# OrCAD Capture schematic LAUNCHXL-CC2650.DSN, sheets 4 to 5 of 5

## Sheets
4 2_Peripherals: size A3
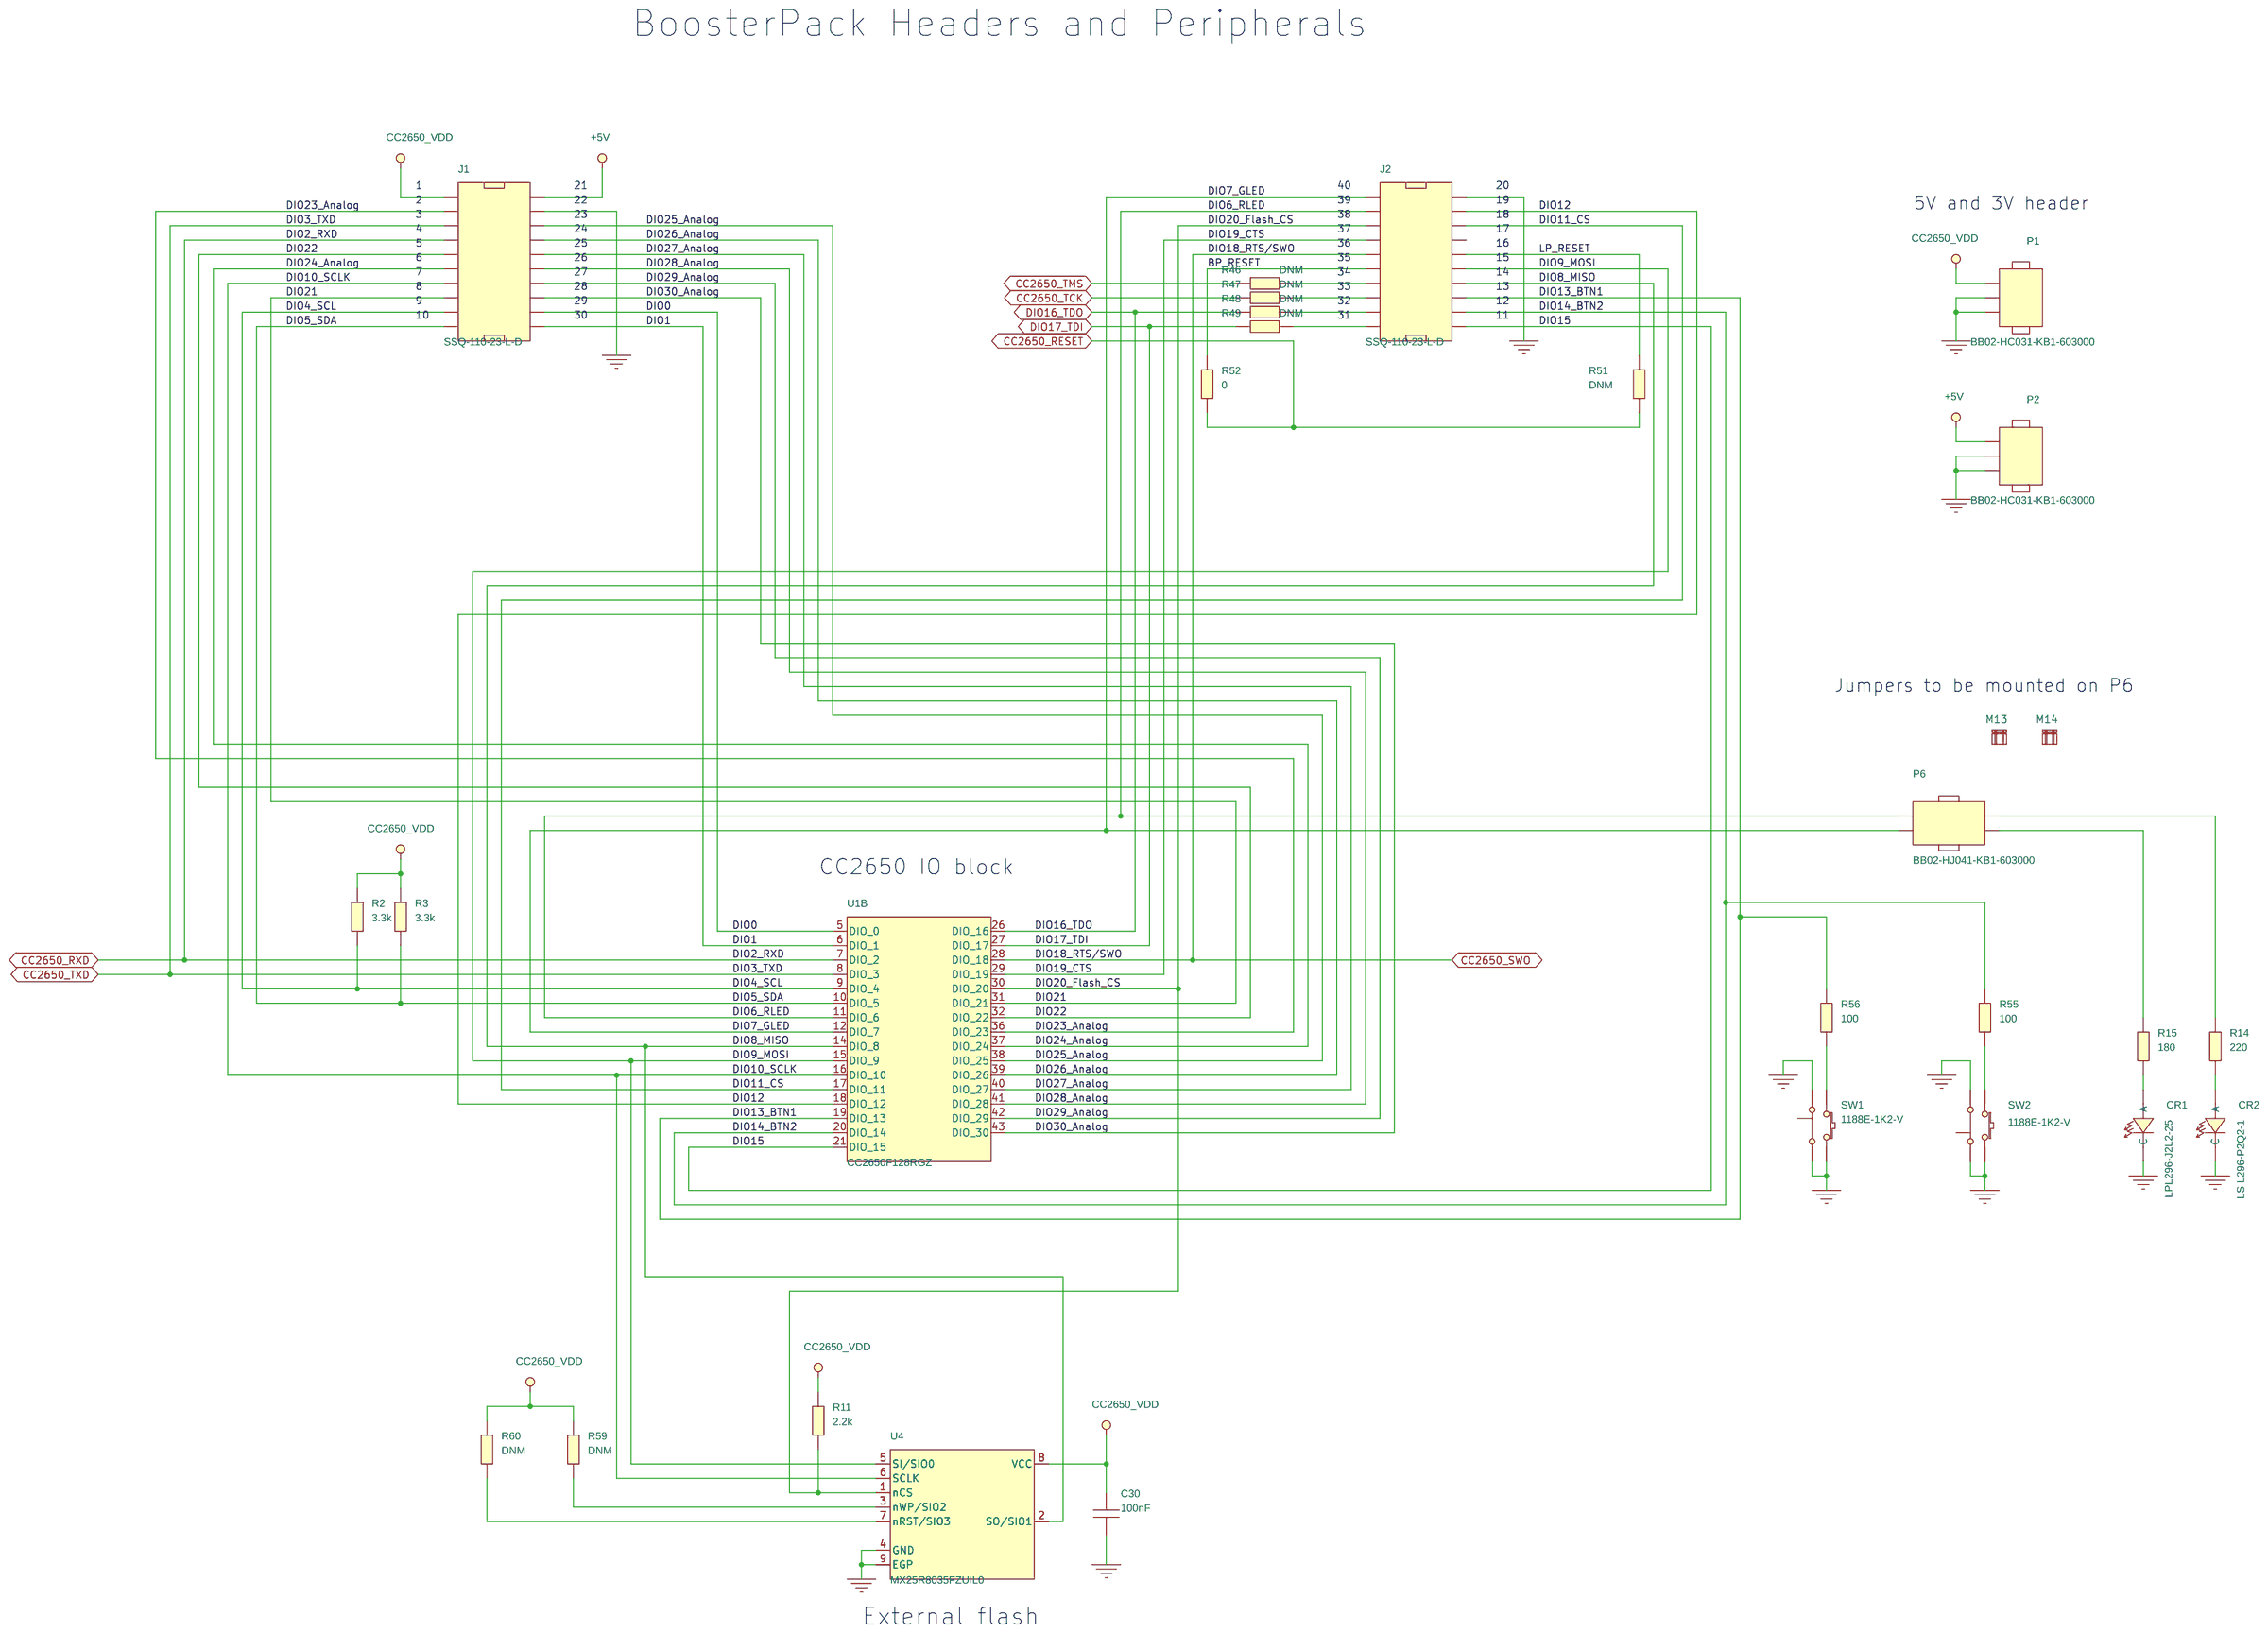
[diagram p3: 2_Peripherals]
5 1_CC2650RF: size A4
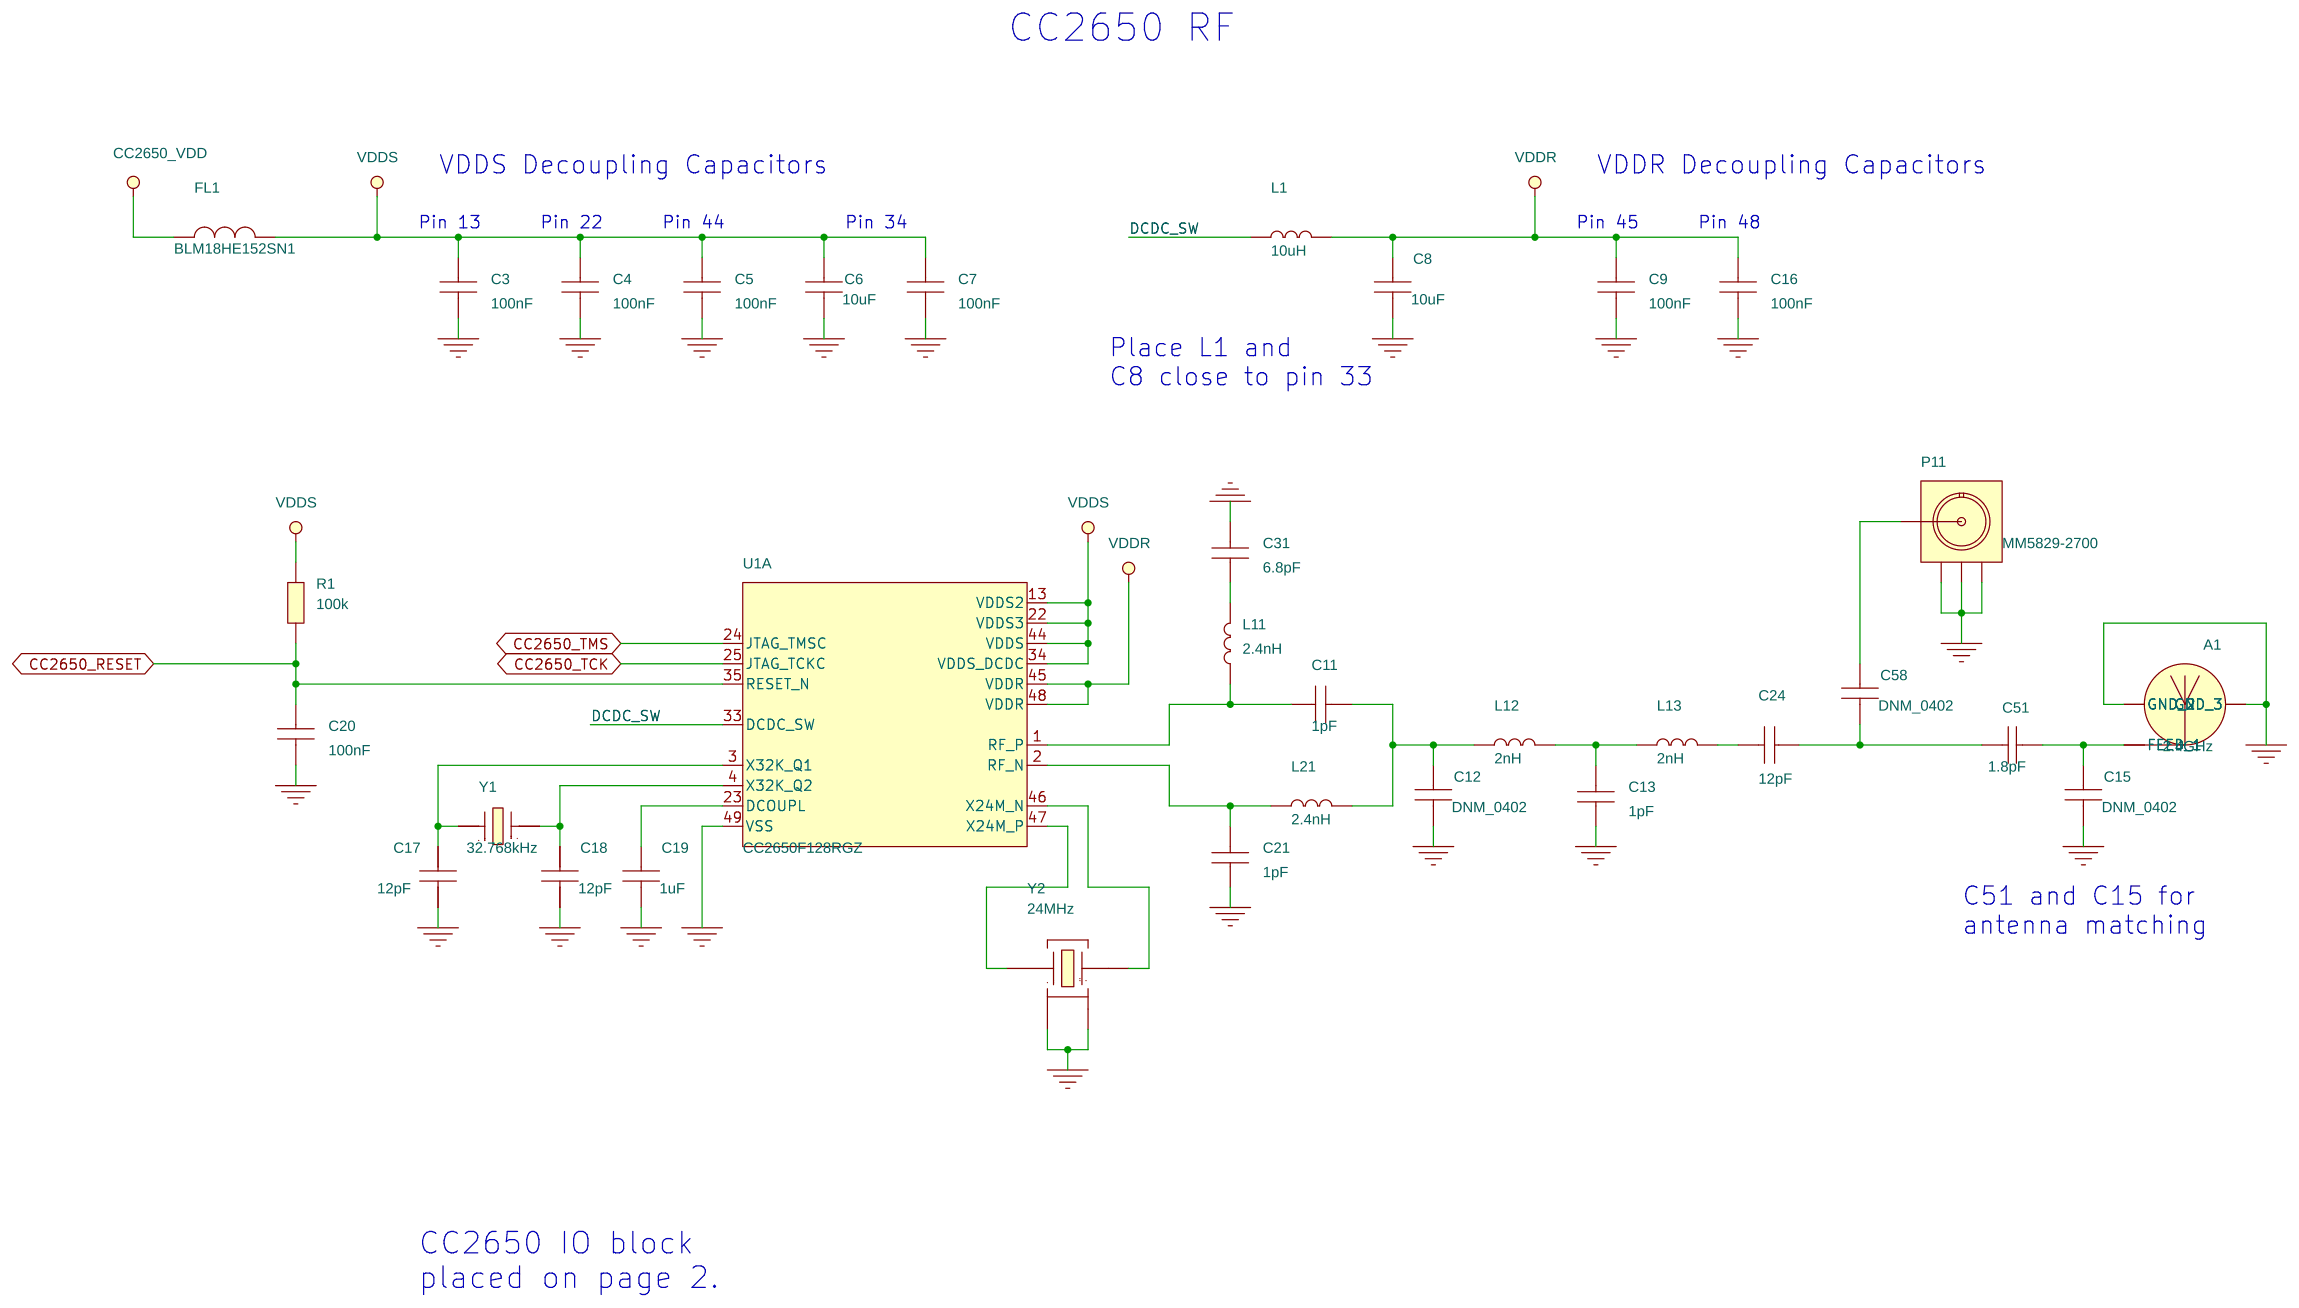
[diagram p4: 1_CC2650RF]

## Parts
sheet 1_CC2650RF
A1  2.4GHz  [ANTENNA_DN007AN]
C3  100nF  [CAPC1005X60B2N]
C4  100nF  [CAPC1005X60B2N]
C5  100nF  [CAPC1005X60B2N]
C6  10uF  [CAPC1608X90N]
C7  100nF  [CAPC1005X60B2N]
C8  10uF  [CAPC1608X90N]
C9  100nF  [CAPC1005X60B2N]
C11  1pF  [CAPC1005X60B2N]
C12  DNM_0402  [CAPC1005X60B2N]
C13  1pF  [CAPC1005X60B2N]
C15  DNM_0402  [CAPC1005X60B2N]
C16  100nF  [CAPC1005X60B2N]
C17  12pF  [CAPC1005X60B2N]
C18  12pF  [CAPC1005X60B2N]
C19  1uF  [CAPC1005X60B2N]
C20  100nF  [CAPC1005X60B2N]
C21  1pF  [CAPC1005X60B2N]
C24  12pF  [CAPC1005X60B2N]
C31  6.8pF  [CAPC1005X60N]
C51  1.8pF  [CAPC1005X60B2N]
C58  DNM_0402  [CAPC1005X60B2N]
FL1  BLM18HE152SN1  [FIL_BLM18HE152SN1DL]
L1  10uH  [INDC2012X150L]
L11  2.4nH  [INDC1005X60B2N]
L12  2nH  [INDC1005X60B2N]
L13  2nH  [INDC1005X60B2N]
L21  2.4nH  [INDC1005X60B2N]
P11  MM5829-2700  [MURATA_MM58292700RJ4_A2N]
R1  100k  [RESC1005X40B2N]
U1  CC2650F128RGZ  [QFNFC50P700X700X80-49CL]  (sections A,B)
Y1  32.768kHz  [XTAL_FC-135N]
Y2  24MHz  [OSCCC250X320X60-4L]
sheet 2_Peripherals
C30  100nF  [CAPC1005X60B2N]
CR1  LPL296-J2L2-25  [LEDC1707X65L]
CR2  LS L296-P2Q2-1  [LEDC1708X67L]
J1  SSQ-110-23-L-D  [SAMTEC_SSQ11023LD_A2B]
J2  SSQ-110-23-L-D  [SAMTEC_SSQ11023LD_A2B]
M13  SNT-100-BK-G
M14  SNT-100-BK-G
P1  BB02-HC031-KB1-603000  [GRADCONN_BB02HC031KB1603000_A2B]
P2  BB02-HC031-KB1-603000  [GRADCONN_BB02HC031KB1603000_A2B]
P6  BB02-HJ041-KB1-603000  [GRADCONN_BB02HJ041KB1603000_A2B]
R2  3.3k  [RESC1005X40B2N]
R3  3.3k  [RESC1005X40B2N]
R11  2.2k  [RESC1005X40B2N]
R14  220  [RESC1005X40B2N]
R15  180  [RESC1005X40B2N]
R46  DNM  [RESC1608X55N]
R47  DNM  [RESC1608X55N]
R48  DNM  [RESC1608X55N]
R49  DNM  [RESC1608X55N]
R51  DNM  [RESC1608X55N]
R52  0  [RESC1608X55N]
R55  100  [RESC1005X40B2N]
R56  100  [RESC1005X40B2N]
R59  DNM  [RESC1005X40B2N]
R60  DNM  [RESC1005X40B2N]
SW1  1188E-1K2-V  [SW_1188E1K2V_A2N]
SW2  1188E-1K2-V  [SW_1188E1K2V_A2N]
U4  MX25R8035FZUIL0  [SON50P300X200X60-9B2L]

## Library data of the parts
A1 = ANTENNA_DN007: MECHANIC, 2.4GHz INVERTED F ANTENNA, SMD; AutoDoc File: http://notefied-dynamic-precision.com/DB/Apps/Desktop/Item/Object.aspx?id=85542; Budget Currency: N/A; Budget Price: N/A; Datasheet URL 1: http://www.ti.com/lit/er/swrz002d/swrz002d.pdf; Datasheet URL 2: http://www.ti.com/lit/ds/symlink/cc2500.pdf; Definied Quality: INDUSTRIAL; Esd Level: HBM 500V; FPLIST: ANTENNA_DN007N,ANTENNA_DN007AN,; Last Time Buy: N/A; Lead Time: N/A; MPN: DN007; MPN Status: ACTIVE; MSL: N/A; MTBF: N/A; MTBF Standard: N/A; Manufacturer: TEXAS INSTRUMENTS; Max Oper Temp: +85DEGC; Min Oper Temp: -40DEGC; Mounting Type: SMD; NOTE Status: PREFERRED; Old Footprint: ANTENNA_DN007N,ANTENNA_DN007AN; Packing Size: N/A; Packing Type: N/A; Part Number: 13-00347; Part Type: MECHANIC\ANTENNA; Revision: R006; RoHS Status: LEADED; WEIGHT: N/A
C3-C5 C7 C9 C16 C20 = CAPACITOR: CAPACITOR, CERAMIC X7R, 100nF, 6.3V, -10%/+10%, -55DEGC/+125DEGC, 0402, SMD; AutoDoc File: https://notefied-dynamic-precision.com/DB/Apps/Desktop/Item/Object.aspx?id=113338; BU Name: TEXAS INSTRUMENTS NORWAY; Budget Currency: EUR; Budget Price: 0.007; Country of Origin: PHILIPPINES; Datasheet URL 1: http://psearch.murata.com/capacitor/product/GRM155R70J104KA01%23.pdf; Datasheet URL 2: http://search.murata.co.jp/Ceramy/image/img/w_hinm/L0005E.pdf; Dielectric Type: X7R; Last Time Buy: N/A; Lead Time: 14; LifeCycle Status: ACTIVE; MPN: GRM155R70J104KA01D; MPN Status: ACTIVE; Manufacturer: MURATA; Max Oper Temp: +125DEGC; Max Tol: +10%; Min Oper Temp: -55DEGC; Min Tol: -10%; Mounting Type: SMD; NOTE Status: PREFERRED; Old Footprint: CAPC1005X60N,0402; PCB Package: 0402; Packing Size: 10000; Packing Type: TAPE_&_REEL; Part Number: 02-07610; Part Type: CAPACITOR\CERAMIC\0402\STANDARD; Revision: R000; RoHS Status: ROHS_COMPLIANT; Rtd Voltage: 6.3V; Vendor: MURATA; Vendor Part Number: GRM155R70J104KA01D; Vendor Part Status: NRND; WEIGHT: 0.0016g
C6 C8 = CAPACITOR: CAPACITOR, CERAMIC X5R, 10uF, 6.3V, -20%/+20%, -55DEGC/+85DEGC, 0603, SMD; ALT_SYMBOLS: CAPC1608X90L,CAPC1608X90M; AutoDoc File: http://notefied-dynamic-precision.com/DB/Apps/Desktop/Item/Object.aspx?id=74686; Budget Currency: EUR; Budget Price: 0.067; Datasheet URL 1: http://search.murata.co.jp/Ceramy/image/img/w_hinm/L0005E.pdf; Datasheet URL 2: http://psearch.murata.com/capacitor/product/GRM188R60J106ME47%23.pdf; Definied Quality: INDUSTRIAL; Dielectric Type: X5R; Esd Level: N/A; FPLIST: CAPC1608X90N,CAPC1608X90L,CAPC1608X90M; Last Time Buy: N/A; Lead Time: 20; MPN: GRM188R60J106ME47D; MPN Status: NRND; MSL: 1; MTBF: N/A; MTBF Standard: N/A; Manufacturer: MURATA; Max Oper Temp: +85DEGC; Max Tol: +20%; Min Oper Temp: -55DEGC; Min Tol: -20%; Mounting Type: SMD; NOTE Status: PREFERRED; PCB Package: 0603; Packing Size: 4000; Packing Type: TAPE_&_REEL; Part Number: 02-02419; Part Type: CAPACITOR\CERAMIC\0603; Revision: R003; RoHS Status: ROHS_COMPLIANT; Rtd Voltage: 6.3V; WEIGHT: 0.0063g
C11 C13 C21 = CAPACITOR: CAPACITOR, CERAMIC C0G/NP0, 1pF, 50V, -0.25pF/ +0.25pF, -55DEGC/+125DEGC, 0402, SMD; AutoDoc File: https://notefied-dynamic-precision.com/DB/Apps/Desktop/Item/Object.aspx?id=113355; BU Name: TEXAS INSTRUMENTS NORWAY; Budget Currency: EUR; Budget Price: 0.006; Country of Origin: PHILIPPINES; Datasheet URL 1: http://psearch.murata.com/capacitor/product/GRM1555C1H1R0CA01%23.pdf; Datasheet URL 2: http://search.murata.co.jp/Ceramy/image/img/w_hinm/L0005E.pdf; Dielectric Type: C0G/NP0; Last Time Buy: N/A; Lead Time: 12; MPN: GRM1555C1H1R0CA01D; MPN Status: ACTIVE; Manufacturer: MURATA; Max Oper Temp: +125DEGC; Max Tol: +0.25pF; Min Oper Temp: -55DEGC; Min Tol: -0.25pF; Mounting Type: SMD; NOTE Status: PREFERRED; Old Footprint: CAPC1005X60N; PCB Package: 0402; Packing Size: 10000; Packing Type: TAPE_&_REEL; Part Number: 02-07627; Part Type: CAPACITOR\CERAMIC\0402\STANDARD; Revision: R000; RoHS Status: ROHS_COMPLIANT; Rtd Voltage: 50V; Vendor: MURATA; Vendor Part Number: GRM1555C1H1R0CA01D; Vendor Part Status: ACTIVE; WEIGHT: 0.0016g
C12 C15 C58 = CAPACITOR: CAPACITOR, CERAMIC, TBD, -55DEGC/+125DEGC, 0402, DNM, SMD; AutoDoc File: https://notefied-dynamic-precision.com/DB/Apps/Desktop/Item/Object.aspx?id=113344; BU Name: TEXAS INSTRUMENTS NORWAY; Budget Currency: USD; Budget Price: 0.00589; Country of Origin: MISSING INFO; Datasheet URL 1: N/A; Datasheet URL 2: N/A; Dielectric Type: MISSING-INFO; Last Time Buy: N/A; Lead Time: N/A; MPN: CAPACITOR_0402_DNM_N/A_M; MPN Status: ACTIVE; Manufacturer: Manufacturer selection; Max Oper Temp: +125DEGC; Min Oper Temp: -55DEGC; Mounting Type: SMD; NOTE Status: PREFERRED; Old Footprint: CAPC1005X60N; PCB Package: 0402; Packing Size: 10000; Packing Type: TAPE_&_REEL; Part Number: 02-07616; Part Type: CAPACITOR\CERAMIC\0402\STANDARD; Revision: R000; RoHS Status: MISSING_INFO; Vendor: MANUFACTURER SELECTION; Vendor Part Number: CAPACITOR_0402_DNM_N/A_M; Vendor Part Status: ACTIVE; Weight: N/A
C17 C18 = CAPACITOR: CAPACITOR, CERAMIC C0G/NP0, 12pF, 50V, -5%/+5%, -55DEGC/+125DEGC, 0402, SMD; AutoDoc File: https://notefied-dynamic-precision.com/DB/Apps/Desktop/Item/Object.aspx?id=113340; BU Name: TEXAS INSTRUMENTS NORWAY; Budget Currency: USD; Budget Price: 0.00589; Country of Origin: MISSING INFO; Datasheet URL 1: N/A; Datasheet URL 2: N/A; Definied Quality: INDUSTRIAL; Dielectric Type: C0G/NP0; Esd Level: N/A; Last Time Buy: N/A; Lead Time: N/A; LifeCycle Status: ACTIVE; MPN: CAPACITOR_0402_12pF_C0G/NP0_M_+/-5%_50V; MPN Status: ACTIVE; MSL: N/A; MTBF: N/A; MTBF Standard: N/A; Manufacturer: MANUFACTURER SELECTION; Max Oper Temp: +125DEGC; Max Tol: +5%; Min Oper Temp: -55DEGC; Min Tol: -5%; Mounting Type: SMD; NOTE Status: PREFERRED; Old Footprint: CAPC1005X60N; PCB Package: 0402; Packing Size: 10000; Packing Type: TAPE_&_REEL; Part Number: 02-07612; Part Type: CAPACITOR\CERAMIC\0402\STANDARD; Revision: R000; RoHS Status: ROHS_COMPLIANT; Rtd Voltage: 50V; Vendor: MANUFACTURER SELECTION; Vendor Part Number: CAPACITOR_0402_12pF_C0G/NP0_M_+/-5%_50V; Vendor Part Status: ACTIVE; WEIGHT: N/A
C19 = CAPACITOR: CAPACITOR, CERAMIC X5R, 1uF, 10V, -10%/+10%, -55DEGC/+85DEGC, 0402, SMD; AutoDoc File: https://notefied-dynamic-precision.com/DB/Apps/Desktop/Item/Object.aspx?id=113339; BU Name: TEXAS INSTRUMENTS NORWAY; Budget Currency: EUR; Budget Price: 0.019; Country of Origin: PHILIPPINES,CHINA; Datasheet URL 1: http://psearch.murata.com/capacitor/product/GRM155R61A105KE15%23.pdf; Datasheet URL 2: http://search.murata.co.jp/Ceramy/image/img/w_hinm/L0005E.pdf; Definied Quality: INDUSTRIAL; Dielectric Type: X5R; Esd Level: N/A; Last Time Buy: N/A; Lead Time: 12; MPN: GRM155R61A105KE15D; MPN Status: ACTIVE; MSL: 1; MTBF: N/A; MTBF Standard: N/A; Manufacturer: MURATA; Max Oper Temp: +85DEGC; Max Tol: +10%; Min Oper Temp: -55DEGC; Min Tol: -10%; Mounting Type: SMD; NOTE Status: PREFERRED; Old Footprint: CAPC1005X60N,0402; PCB Package: 0402; Packing Size: 10000; Packing Type: TAPE_&_REEL; Part Number: 02-07611; Part Type: CAPACITOR\CERAMIC\0402\STANDARD; Revision: R000; RoHS Status: ROHS_COMPLIANT; Rtd Voltage: 10V; Vendor: MURATA; Vendor Part Number: GRM155R61A105KE15D; Vendor Part Status: NRND; WEIGHT: 0.0016g
C24 = CAPACITOR: CAPACITOR, CERAMIC C0G/NP0, 12pF, 50V, -5%/+5%, -55DEGC/+125DEGC, 0402, SMD; AutoDoc File: https://notefied-dynamic-precision.com/DB/Apps/Desktop/Item/Object.aspx?id=113345; BU Name: TEXAS INSTRUMENTS NORWAY; Budget Currency: EUR; Budget Price: 0.007; Country of Origin: PHILIPPINES; Datasheet URL 1: http://psearch.murata.com/capacitor/product/GRM1555C1H120JA01%23.pdf; Datasheet URL 2: http://search.murata.co.jp/Ceramy/image/img/w_hinm/L0005E.pdf; Dielectric Type: C0G/NP0; Last Time Buy: N/A; Lead Time: 12; MPN: GRM1555C1H120JA01D; MPN Status: ACTIVE; Manufacturer: MURATA; Max Oper Temp: +125DEGC; Max Tol: +5%; Min Oper Temp: -55DEGC; Min Tol: -5%; Mounting Type: SMD; NOTE Status: PREFERRED; Old Footprint: CAPC1005X60N; PCB Package: 0402; Packing Size: 10000; Packing Type: TAPE_&_REEL; Part Number: 02-07617; Part Type: CAPACITOR\CERAMIC\0402\STANDARD; Revision: R000; RoHS Status: ROHS_COMPLIANT; Rtd Voltage: 50V; Vendor: MURATA; Vendor Part Number: GRM1555C1H120JA01D; Vendor Part Status: ACTIVE; WEIGHT: 0.0016g
C31 = CAPACITOR: CAPACITOR, CERAMIC C0G/NP0, 6.8pF, 50V, -0.25pF/+0.25pF, -55DEGC/+125DEGC, 0402, SMD; ALT_SYMBOLS: CAPC1005X60L,CAPC1005X60M; AutoDoc File: https://notefied-dynamic-precision.com/DB/Apps/Desktop/Item/Object.aspx?id=84868; BU Name: DYNAMIC PRECISION GDANSK; Budget Currency: EUR; Budget Price: 0.007; Country of Origin: PHILIPPINES; Datasheet URL 1: http://psearch.murata.com/capacitor/product/GRM1555C1H6R8CA01%23.pdf; Datasheet URL 2: http://search.murata.co.jp/Ceramy/image/img/w_hinm/L0005E.pdf; Dielectric Type: C0G/NP0; Last Time Buy: N/A; Lead Time: 16; MPN: GRM1555C1H6R8CA01D; MPN Status: ACTIVE; Manufacturer: MURATA; Max Oper Temp: +125DEGC; Max Tol: +0.25pF; Min Oper Temp: -55DEGC; Min Tol: -0.25pF; Mounting Type: SMD; NOTE Status: PREFERRED; PCB Package: 0402; Packing Size: 10000; Packing Type: TAPE_&_REEL; Part Number: 02-04169; Part Type: CAPACITOR\CERAMIC\0402\STANDARD; Revision: R000; RoHS Status: ROHS_COMPLIANT; Rtd Voltage: 50V; Vendor: MURATA; Vendor Part Number: GRM1555C1H6R8CA01D; Vendor Part Status: ACTIVE; WEIGHT: 0.0016g
C51 = CAPACITOR_HOR: CAPACITOR, CERAMIC C0G/NP0, 1.8pF, 50V, -0.25pF, +0.25pF, -55DEGC/+125DEGC, 0402, SMD; AutoDoc File: https://notefied-dynamic-precision.com/DB/Apps/Desktop/Item/Object.aspx?id=113348; BU Name: TEXAS INSTRUMENTS NORWAY; Budget Currency: EUR; Budget Price: 0.007; Country of Origin: PHILIPPINES; Datasheet URL 1: http://psearch.murata.com/capacitor/product/GRM1555C1H1R8CA01%23.pdf; Datasheet URL 2: http://search.murata.co.jp/Ceramy/image/img/w_hinm/L0005E.pdf; Definied Quality: INDUSTRIAL; Dielectric Type: C0G/NP0; Esd Level: N/A; Last Time Buy: N/A; Lead Time: 12; LifeCycle Status: ACTIVE; MPN: GRM1555C1H1R8CA01D; MPN Status: ACTIVE; MSL: 1; MTBF: N/A; MTBF Standard: N/A; Manufacturer: MURATA; Max Oper Temp: +125DEGC; Max Tol: +0.25pF; Min Oper Temp: -55DEGC; Min Tol: -0.25pF; Mounting Type: SMD; NOTE Status: PREFERRED; Old Footprint: CAPC1005X60N; PCB Package: 0402; Packing Size: 10000; Packing Type: TAPE_&_REEL; Part Number: 02-07620; Part Type: CAPACITOR\CERAMIC\0402\STANDARD; Revision: R000; RoHS Status: ROHS_COMPLIANT; Rtd Voltage: 50V; Vendor: MURATA; Vendor Part Number: GRM1555C1H1R8CA01D; Vendor Part Status: ACTIVE; WEIGHT: 0.0016g
FL1 = FILTER_2PIN: FILTER, EMI, 1500@100MHz, -55DEGC/+125DEGC, 0603, SMD; ALT_SYMBOLS: FIL_BLM18HE152SN1DL,FIL_BLM18HE152SN1DM; AutoDoc File: http://notefied-dynamic-precision.com/DB/Apps/Desktop/Item/Object.aspx?id=85575; Budget Currency: EUR; Budget Price: 0.085; Datasheet URL 1: http://search.murata.co.jp/Ceramy/image/img/PDF/ENG/L0110S0101BLM18H.pdf; Datasheet URL 2: http://search.murata.co.jp/Ceramy/image/img/PDF/ENG/L0110S0101BLM18H.pdf; FPLIST: FIL_BLM18HE152SN1DN,FIL_BLM18HE152SN1DL,FIL_BLM18HE152SN1DM; Impedance: 1500@100MHz; Lead Time: 26; MPN: BLM18HE152SN1D; MPN Status: ACTIVE; Manufacturer: MURATA; Max Oper Temp: +125DEGC; Max Tol: +25%; Min Oper Temp: -55DEGC; Min Tol: -25%; Mounting Type: SMD; NOTE Status: PREFERRED; Old Footprint: FIL_BLM18HE152SN1DN; PCB Package: 0603; Packing Size: 4000; Packing Type: TAPE_&_REEL; Part Number: 04-00470; Part Type: FILTER\EMI\0603; Revision: R001; RoHS Status: ROHS_COMPLIANT; Rtd Current: 0.5A; WEIGHT: 0.006g
L1 = INDUCTOR: INDUCTOR, CHIP, 10uH, -20%/+20%, 0.11A, -40DEGC/+85DEGC, 0805, SMD; ALT_SYMBOLS: INDC2012X150L,INDC2012X150M; AutoDoc File: http://notefied-dynamic-precision.com/DB/Apps/Desktop/Item/Object.aspx?id=84960; Budget Currency: USD; Budget Price: 0.04; Datasheet URL 1: http://www.yuden.co.jp/us/product/pdf/mlci_all_e.pdf; Datasheet URL 2: http://www.yuden.co.jp/us/product/pdf/mlci_all_e.pdf; FPLIST: INDC2012X150N,INDC2012X150L,INDC2012X150M; Frequency: 24MHz; MPN: CKS2125100M-T; MPN Status: ACTIVE; Manufacturer: TAIYO YUDEN; Max Oper Temp: +85DEGC; Max Tol: +20%; Min Oper Temp: -40DEGC; Min Tol: -20%; Mounting Type: SMD; NOTE Status: PREFERRED; Old Footprint: INDC2012X150N; PCB Package: 0805; Packing Size: 4000; Packing Type: TAPE_&_REEL; Part Number: 03-06514; Part Type: INDUCTOR\CHIP\0805; Revision: R001; RoHS Status: ROHS_COMPLIANT; Rtd Current: 0.11A
L11 L21 = INDUCTOR: INDUCTOR, RF, CHIP, NON-MAGNETIC CORE, 2.4nH, -0.3nH/+0.3nH, 0.3A, -55DEGC/+125DEGC, 0402, SMD; AutoDoc File: https://notefied-dynamic-precision.com/DB/Apps/Desktop/Item/Object.aspx?id=113363; BU Name: TEXAS INSTRUMENTS NORWAY; Budget Currency: EUR; Budget Price: 0.031; Core Material: NON-MAGNETIC; Country of Origin: JAPAN,SINGAPORE; Datasheet URL 1: http://psearch.murata.com/inductor/product/LQG15HS2N4S02%23.pdf; Datasheet URL 2: N/A; Frequency: 6GHz; Last Time Buy: N/A; Lead Time: 9; MPN: LQG15HN2N4S02D; MPN Status: ACTIVE; Manufacturer: MURATA; Max Oper Temp: +125DEGC; Max Tol: +0.3nH; Min Oper Temp: -55DEGC; Min Tol: -0.3nH; Mounting Type: SMD; NOTE Status: PREFERRED; Old Footprint: INDC1005X60N; PCB Package: 0402; Packing Size: 10000; Packing Type: TAPE_&_REEL; Part Number: 03-07526; Part Type: INDUCTOR\RF\CHIP\0402; Revision: R000; RoHS Status: ROHS_COMPLIANT; Rtd Current: 0.3A; Vendor: MURATA; Vendor Part Number: LQG15HS2N4S02D; Vendor Part Status: ACTIVE; WEIGHT: 0.001g
L12 L13 = INDUCTOR: INDUCTOR, RF, CHIP, NON-MAGNETIC CORE, 2nH, -0.3nH/+0.3nH, 0.3A, -55DEGC/+125DEGC, 0402, SMD; AutoDoc File: https://notefied-dynamic-precision.com/DB/Apps/Desktop/Item/Object.aspx?id=113364; BU Name: TEXAS INSTRUMENTS NORWAY; Budget Currency: EUR; Budget Price: 0.031; Core Material: NON-MAGNETIC; Country of Origin: JAPAN,SINGAPORE; Datasheet URL 1: http://psearch.murata.com/inductor/product/LQG15HS2N0S02%23.pdf; Datasheet URL 2: N/A; Frequency: 6GHz; Last Time Buy: N/A; Lead Time: 10; MPN: LQG15HS2N0S02D; MPN Status: ACTIVE; Manufacturer: MURATA; Max Oper Temp: +125DEGC; Max Tol: +0.3nH; Min Oper Temp: -55DEGC; Min Tol: -0.3nH; Mounting Type: SMD; NOTE Status: PREFERRED; Old Footprint: INDC1005X60N; PCB Package: 0402; Packing Size: 10000; Packing Type: TAPE_&_REEL; Part Number: 03-07527; Part Type: INDUCTOR\RF\CHIP\0402; Revision: R000; RoHS Status: ROHS_COMPLIANT; Rtd Current: 0.3A; Vendor: MURATA; Vendor Part Number: LQG15HS2N0S02D; Vendor Part Status: ACTIVE; WEIGHT: 0.001g
P11 = CONN_COAX_1_1_P_2MH_V1: CONNECTOR, COAX, MALE, UP TO 12GHz, 30V, SMD; ALT_SYMBOLS: MURATA_MM58292700RJ4_A2L,MURATA_MM58292700RJ4_A2M; AutoDoc File: http://notefied-dynamic-precision.com/DB/Apps/Desktop/Item/Object.aspx?id=105030; Datasheet URL 1: http://search.murata.co.jp/Ceramy/image/img/w_hinm/L0390E.pdf; Datasheet URL 2: http://www.murata.com/~/media/webrenewal/support/library/catalog/products/switch/switch/o33e.ashx; FPLIST: MURATA_MM58292700RJ4_A2N,MURATA_MM58292700RJ4_A2L,MURATA_MM58292700RJ4_A2M; Frequency: 12GHz; Impedance: 50; MPN: MM5829-2700RJ4; MPN Status: ACTIVE; Manufacturer: MURATA; Max Oper Temp: +85DEGC; Min Oper Temp: -40DEGC; Mounting Type: SMD; NOTE Status: PREFERRED; Packing Size: 4000; Packing Type: TAPE_&_REEL; Part Number: 06-05051; Part Type: CONNECTOR\COAX; Revision: R002; RoHS Status: ROHS_COMPLIANT; Rtd Power: 2W; Rtd Voltage: 30V
R1 = RESISTOR: RESISTOR, THICK FILM, 100k, -1%/+1%, 0.063W, 50V, -55DEGC/+155DEGC, 0402, SMD; AutoDoc File: https://notefied-dynamic-precision.com/DB/Apps/Desktop/Item/Object.aspx?id=113333; BU Name: TEXAS INSTRUMENTS NORWAY; Budget Currency: USD; Budget Price: 0.00244; Country of Origin: MISSING INFO; Datasheet URL 1: N/A; Datasheet URL 2: N/A; Definied Quality: INDUSTRIAL; Esd Level: N/A; Last Time Buy: N/A; Lead Time: N/A; LifeCycle Status: ACTIVE; MPN: RESISTOR_0402_100k_+/-1%_50V_0.063W_M_+/-100PPM; MPN Status: ACTIVE; MSL: N/A; MTBF: N/A; MTBF Standard: N/A; Manufacturer: MANUFACTURER SELECTION; Max Oper Temp: +155DEGC; Max TC: +100PPM/DEGC; Max Tol: +1%; Min Oper Temp: -55DEGC; Min TC: -100PPM/DEGC; Min Tol: -1%; Mounting Type: SMD; NOTE Status: PREFERRED; Old Footprint: RESC1005X40N; PCB Package: 0402; Packing Size: 10000; Packing Type: TAPE_&_REEL; Part Number: 01-22360; Part Type: RESISTOR\0402\PRECISION; Resistor Type: THICK FILM; Revision: R000; RoHS Status: ROHS_COMPLIANT; Rtd Current: N/A; Rtd Power: 0.063W; Rtd Voltage: 50V; Vendor: MANUFACTURER SELECTION; Vendor Part Number: RESISTOR_0402_100k_+/-1%_50V_0.063W_M_+/-100ppm; Vendor Part Status: ACTIVE; WEIGHT: N/A
U1 = IC_RF_CC26XX_QFN48_V2: IC, DIGITAL, TEXAS INSTRUMENTS CUSTOM 26xx, QFN48, SMD; ALT_SYMBOLS: QFNFC50P700X700X80-49CL,QFNFC50P700X700X80-49CM; AutoDoc File: http://notefied-dynamic-precision.com/DB/Apps/Desktop/Item/Object.aspx?id=88778; FPLIST: QFNFC50P700X700X80-49CN,QFNFC50P700X700X80-49CL,QFNFC50P700X700X80-49CM; MPN: CC26xx_7x7_QFN48; MPN Status: ACTIVE; Manufacturer: TEXAS INSTRUMENTS; Mounting Type: SMD; NOTE Status: PREFERRED; Old Footprint: QFNFC50P700X700X80-49CN; PCB Package: QFN48; Part Number: 18-28499; Part Type: IC\OTHER; Revision: R001; RoHS Status: ROHS_COMPLIANT; Budget Currency: N/A; Budget Price: N/A; Datasheet URL 1: http://www.ti.com/litv/pdf/mpqf123e; Datasheet URL 2: http://www.ti.com/lit/ds/symlink/cc2650.pdf; Definied Quality: COMMERCIAL; Esd Level: N/A; Last Time Buy: N/A; Lead Time: N/A; LifeCycle Status: PRELIMINARY; MSL: N/A; MTBF: N/A; MTBF Standard: N/A; Max Oper Temp: +85DEGC; Min Oper Temp: -40DEGC; Packing Size: 2500; Packing Type: TAPE_&_REEL; Rtd Voltage: 3.8V; WEIGHT: N/A
Y1 = CRYSTAL: CRYSTAL, RESONATOR, 32.768kHz, -20PPM/+20PPM, -40DEGC/+85DEGC, SMD; ALT_SYMBOLS: XTAL_FC-135L,XTAL_FC-135M; AutoDoc File: http://notefied-dynamic-precision.com/DB/Apps/Desktop/Item/Object.aspx?id=91966; Budget Currency: USD; Budget Price: 1.25375; Capacitance: 7pF; Datasheet URL 1: http://www.eea.epson.com/portal/pls/portal/docs/1/1525528.PDF; Datasheet URL 2: http://www.eea.epson.com/portal/pls/portal/docs/1/1525451.PDF; Definied Quality: INDUSTRIAL; Esd Level: N/A; FPLIST: XTAL_FC-135N,XTAL_FC-135L,XTAL_FC-135M; Last Time Buy: N/A; Lead Time: 10; MPN: FC-135 32.7680KA-AG0; MPN Status: ACTIVE; MSL: N/A; MTBF: N/A; MTBF Standard: N/A; Manufacturer: EPSON; Max Oper Temp: +85DEGC; Max Tol: +20PPM; Min Oper Temp: -40DEGC; Min Tol: -20PPM; Mounting Type: SMD; NOTE Status: PREFERRED; Packing Size: 1000; Packing Type: TAPE_&_REEL; Part Number: 12-00546; Part Type: CRYSTAL\OSCILLATOR\MEMS; Revision: R001; RoHS Status: ROHS_COMPLIANT; WEIGHT: N/A
Y2 = XTAL_4PIN_S: CRYSTAL, CRYSTAL OSCILLATOR, 24MHz, -15PPM/DEGC/+15PPM/DEGC, -40DEGC/+85DEGC, SMD; ALT_SYMBOLS: OSCCC250X320X60-4L,OSCCC250X320X60-4M; AutoDoc File: http://notefied-dynamic-precision.com/DB/Apps/Desktop/Item/Object.aspx?id=96738; Budget Currency: EUR; Budget Price: 0.256; Capacitance: 9pF; Datasheet URL 1: http://www.eea.epson.com/portal/pls/portal/docs/1/1721495.PDF; Datasheet URL 2: http://www.epsondevice.com/docs/qd/en/DownloadServlet?id=ID000658; FPLIST: OSCCC250X320X60-4N,OSCCC250X320X60-4L,OSCCC250X320X60-4M; Lead Time: 12; MPN: TSX-3225 24.0000MF15X-AC3; MPN Status: ACTIVE; Manufacturer: EPSON; Max Oper Temp: +85DEGC; Max TC: +15PPM/DEGC; Max Tol: +10PPM; Min Oper Temp: -40DEGC; Min TC: -15PPM/DEGC; Min Tol: -10PPM; Mounting Type: SMD; NOTE Status: PREFERRED; Old Footprint: OSCCC250X320X60-4N; Packing Size: 250; Packing Type: TAPE_&_REEL; Part Number: 12-00757; Part Type: CRYSTAL\OSCILLATOR; Revision: R001; RoHS Status: ROHS_COMPLIANT
C30 = CAPACITOR: CAPACITOR, CERAMIC X7R, 100nF, 6.3V, -10%/+10%, -55DEGC/+125DEGC, 0402, SMD; AutoDoc File: https://notefied-dynamic-precision.com/DB/Apps/Desktop/Item/Object.aspx?id=113338; BU Name: TEXAS INSTRUMENTS NORWAY; Budget Currency: EUR; Budget Price: 0.007; Country of Origin: PHILIPPINES; Datasheet URL 1: http://psearch.murata.com/capacitor/product/GRM155R70J104KA01%23.pdf; Datasheet URL 2: http://search.murata.co.jp/Ceramy/image/img/w_hinm/L0005E.pdf; Definied Quality: INDUSTRIAL; Dielectric Type: X7R; Esd Level: N/A; Last Time Buy: N/A; Lead Time: 14; LifeCycle Status: ACTIVE; MPN: CAPACITOR_0402_100nF_X7R_M_+/-10%_10V; MPN Status: ACTIVE; MSL: N/A; MTBF: N/A; MTBF Standard: N/A; Manufacturer: MANUFACTURER SELECTION; Max Oper Temp: +125DEGC; Max Tol: +10%; Min Oper Temp: -55DEGC; Min Tol: -10%; Mounting Type: SMD; NOTE Status: PREFERRED; Old Footprint: CAPC1005X60N; PCB Package: 0402; Packing Size: 10000; Packing Type: TAPE_&_REEL; Part Number: 02-07610; Part Type: CAPACITOR\CERAMIC\0402\STANDARD; Revision: R000; RoHS Status: ROHS_COMPLIANT; Rtd Voltage: 6.3V; Vendor: MURATA; Vendor Part Number: GRM155R70J104KA01D; Vendor Part Status: NRND; WEIGHT: 0.0016g
CR1 = LED: OPTO, LED, GREEN COLOR, 562nm, 0.02A, 0.08W, 0603, SMD; ALT_SYMBOLS: LEDC1707X65L,LEDC1707X65M; AutoDoc File: http://notefied-dynamic-precision.com/DB/Apps/Desktop/Item/Object.aspx?id=81622; Budget Currency: USD; Budget Price: 0.1263; Datasheet URL 1: N/A; Datasheet URL 2: http://catalog.osram-os.com/jsp/download.jsp?rootPath=/media/&name=LP_L296.pdf&docPath=Graphics/00077128_0.pdf&url=/media//_en/Graphics/00077128_0.pdf; Definied Quality: INDUSTRIAL; Esd Level: HBM 2kV; FPLIST: LEDC1707X65N,LEDC1707X65L,LEDC1707X65M; Last Time Buy: N/A; Lead Time: 8; MPN: LP L296-J2L2-25; MPN Status: NRND; MSL: 2; MTBF: N/A; MTBF Standard: N/A; Manufacturer: OSRAM; Max Oper Temp: +100DEGC; Min Oper Temp: -40DEGC; Mounting Type: SMD; NOTE Status: NOT_PREFERRED; Old Footprint: LEDC1707X65N; PCB Package: 0603; Packing Size: 5000; Packing Type: TAPE_&_REEL; Part Number: 15-01023; Part Type: OPTO\LED\0603; Revision: R003; RoHS Status: ROHS_COMPLIANT; Rtd Current: 0.02A; Rtd Power: 0.08W; Rtd Voltage: 2V; WEIGHT: 0.002g
CR2 = LED: OPTO, LED, SUPER RED COLOR, 630nm, 1.8V TO 2.3V, 0.06A, 0603, SMD; ALT_SYMBOLS: LEDC1708X67L,LEDC1708X67M; AutoDoc File: http://notefied-dynamic-precision.com/DB/Apps/Desktop/Item/Object.aspx?id=88355; Budget Currency: USD; Budget Price: 0.089; Datasheet URL 1: http://www.osram-os.com/osram_os/en/products/product-catalog/led-light-emitting-diodes/smartled-0603/ls-l296/index.jsp?search_result=%2fosram_os%2fen%2fsearch%2fadvanced_search.jsp%3faction%3ddosearch%26inp_searchterm_1%3dLS%2bL296-P2Q2-1%26website_name%3; Datasheet URL 2: http://www.osram-os.com/Graphics/XPic5/00077119_0.pdf/LS%20L296%20-%20SMARTLED%200603.pdf; Definied Quality: INDUSTRIAL; Esd Level: HBM 2kV; FPLIST: LEDC1708X67N,LEDC1708X67L,LEDC1708X67M; Last Time Buy: N/A; Lead Time: 8; MPN Status: NRND; MSL: 2; MTBF: N/A; MTBF Standard: N/A; Manufacturer: OSRAM; Max Oper Temp: +100DEGC; Min Oper Temp: -40DEGC; Mounting Type: SMD; NOTE Status: PREFERRED; Old Footprint: LEDC1708X67N; PCB Package: 0603; PPCB Recomendation: Inactive for new design [Alert:0001]; Packing Size: 5000; Packing Type: TAPE_&_REEL; Part Number: 15-01169; Part Type: OPTO\LED\0603; Revision: R003; RoHS Status: ROHS_COMPLIANT; Rtd Current: 0.06A; Rtd Voltage: 1.8V TO 2.3V; WEIGHT: 0.002g
J1 J2 = CONN_HEADER_2X10_J_S_V1: CONNECTOR, HEADER, FEMALE, STRAIGHT, 2 ROWS, 20 ROWS, 2.54mm, PTH; ALT_SYMBOLS: SAMTEC_SSQ11023LD_A2C,SAMTEC_SSQ11023LD_A2A; AutoDoc File: http://notefied-dynamic-precision.com/DB/Apps/Desktop/Item/Object.aspx?id=104387; Budget Currency: USD; Budget Price: 2.14; Datasheet URL 1: http://suddendocs.samtec.com/prints/ssq-1xx-xx-xxx-x-xx-xxx-xx-x-mkt.pdf; Datasheet URL 2: http://suddendocs.samtec.com/catalog_english/ssq_th.pdf; Definied Quality: INDUSTRIAL; Esd Level: N/A; FPLIST: SAMTEC_SSQ11023LD_A2B,SAMTEC_SSQ11023LD_A2C,SAMTEC_SSQ11023LD_A2A; Lead Time: 1; LifeCycle Status: ACTIVE; MPN Status: ACTIVE; MSL: N/A; Manufacturer: SAMTEC; Max Oper Temp: +125DEGC; Min Oper Temp: -55DEGC; Mounting Type: PTH; NOTE Status: PREFERRED; No Of Pos: 20; No Of Rows: 2; Packing Size: 21; Packing Type: BULK; Part Number: 06-04997; Part Type: CONNECTOR\HEADER; Pitch: 2.54mm; Revision: R001; RoHS Status: ROHS_COMPLIANT; Rtd Current: 6.3A; WEIGHT: 2.45594g
M13 M14 = MECH_SHUNT_JUMPER: MECHANIC, SHUNT, CURRENT RATING 4.3A PER PIN, 2.54 X 5.08 X 6.1mm, BLACK; AutoDoc File: http://notefied-dynamic-precision.com/DB/Apps/Desktop/Item/Object.aspx?id=104092; Budget Currency: USD; Budget Price: 0.146; Datasheet URL 1: http://suddendocs.samtec.com/prints/snt-100-xx-x-x-mkt.pdf; Datasheet URL 2: http://suddendocs.samtec.com/catalog_english/snt.pdf; Definied Quality: INDUSTRIAL; Esd Level: N/A; Last Time Buy: N/A; Lead Time: 1; LifeCycle Status: ACTIVE; MPN Status: ACTIVE; MSL: N/A; MTBF: N/A; MTBF Standard: N/A; Manufacturer: SAMTEC; Max Oper Temp: +125DEGC; Min Oper Temp: -55DEGC; Mounting Type: NOT APPLY; NOTE Status: PREFERRED; Packing Size: 1; Packing Type: BULK; Part Number: 19-00498; Part Type: MECHANIC\SHUNT; Revision: R001; RoHS Status: ROHS_COMPLIANT; Rtd Current: 4.3A; WEIGHT: N/A
P1 P2 = CONN_HEADER_3_P_S: CONNECTOR, HEADER, MALE, STRAIGHT, 1 ROW, 3 PINS, PITCH 2.54mm, PTH; ALT_SYMBOLS: GRADCONN_BB02HC031KB1603000_A2C,GRADCONN_BB02HC031KB1603000_A2A; AutoDoc File: http://notefied-dynamic-precision.com/DB/Apps/Desktop/Item/Object.aspx?id=104636; Datasheet URL 1: http://www.gradconn.com/Files/Drawings/BB02-HC.pdf; Datasheet URL 2: http://www.gradconn.com/Files/Specs/BTB-2.54mm-Header-specification.pdf; FPLIST: GRADCONN_BB02HC031KB1603000_A2B,GRADCONN_BB02HC031KB1603000_A2C,GRADCONN_BB02HC031KB1603000_A2A; MPN Status: ACTIVE; Manufacturer: GRADCONN; Max Oper Temp: +105DEGC; Min Oper Temp: -40DEGC; Mounting Type: PTH; NOTE Status: PREFERRED; No Of Pos: 3; No Of Rows: 1; Part Number: 06-05038; Part Type: CONNECTOR\HEADER; Pitch: 2.54mm; Revision: R001; RoHS Status: ROHS_COMPLIANT; Rtd Current: 3A; Rtd Voltage: 250V
P6 = CONN_HEADER_2X2_P: CONNECTOR, HEADER, MALE, STRAIGHT, 2 ROWS, 4 PINS, PITCH 2.54mm, PTH; ALT_SYMBOLS: GRADCONN_BB02HJ041KB1603000_A2C,GRADCONN_BB02HJ041KB1603000_A2A; AutoDoc File: http://notefied-dynamic-precision.com/DB/Apps/Desktop/Item/Object.aspx?id=104391; Datasheet URL 1: http://www.gradconn.com/Files/Drawings/BB02-HJ.pdf; Datasheet URL 2: http://www.gradconn.com/Files/Specs/BTB-2.54mm-Header-specification.pdf; FPLIST: GRADCONN_BB02HJ041KB1603000_A2B,GRADCONN_BB02HJ041KB1603000_A2C,GRADCONN_BB02HJ041KB1603000_A2A; MPN Status: ACTIVE; Manufacturer: GRADCONN; Max Oper Temp: +105DEGC; Min Oper Temp: -40DEGC; Mounting Type: PTH; NOTE Status: PREFERRED; No Of Pos: 4; No Of Rows: 2; Part Number: 06-04999; Part Type: CONNECTOR\HEADER; Pitch: 2.54mm; Revision: R001; RoHS Status: ROHS_COMPLIANT; Rtd Current: 3A
R2 R3 = RESISTOR: RESISTOR, THICK FILM, 3.3k, -5%/+5%, 0.063W, 50V, -55DEGC/+155DEGC, 0402, SMD; AutoDoc File: https://notefied-dynamic-precision.com/DB/Apps/Desktop/Item/Object.aspx?id=113324; BU Name: TEXAS INSTRUMENTS NORWAY; Budget Currency: USD; Budget Price: 0.00244; Country of Origin: MISSING INFO; Datasheet URL 1: N/A; Datasheet URL 2: N/A; Definied Quality: INDUSTRIAL; Esd Level: N/A; Last Time Buy: N/A; Lead Time: N/A; LifeCycle Status: ACTIVE; MPN: RESISTOR_0402_3.3k_+/-5%_50V_0.063W_M_+/-200ppm; MPN Status: ACTIVE; MSL: N/A; MTBF: N/A; MTBF Standard: N/A; Manufacturer: MANUFACTURER SELECTION; Max Oper Temp: +155DEGC; Max TC: +200PPM/DEGC; Max Tol: +5%; Min Oper Temp: -55DEGC; Min TC: -200PPM/DEGC; Min Tol: -5%; Mounting Type: SMD; NOTE Status: PREFERRED; Old Footprint: RESC1005X40N; PCB Package: 0402; Packing Size: 10000; Packing Type: TAPE_&_REEL; Part Number: 01-22351; Part Type: RESISTOR\0402\STANDARD; Resistor Type: THICK FILM; Revision: R000; RoHS Status: ROHS_COMPLIANT; Rtd Current: N/A; Rtd Power: 0.063W; Rtd Voltage: 50V; Vendor: MANUFACTURER SELECTION; Vendor Part Number: RESISTOR_0402_3.3k_+/-5%_50V_0.063W_M_+/-200ppm; Vendor Part Status: ACTIVE; WEIGHT: N/A
R11 = RESISTOR: RESISTOR, THICK FILM, 2.2k, -5%/+5%, 0.063W, 50V, -55DEGC/+155DEGC, 0402, SMD; AutoDoc File: https://notefied-dynamic-precision.com/DB/Apps/Desktop/Item/Object.aspx?id=113323; BU Name: TEXAS INSTRUMENTS NORWAY; Budget Currency: USD; Budget Price: 0.00244; Country of Origin: MISSING INFO; Datasheet URL 1: N/A; Datasheet URL 2: N/A; Definied Quality: INDUSTRIAL; Esd Level: N/A; Last Time Buy: N/A; Lead Time: N/A; LifeCycle Status: ACTIVE; MPN: RESISTOR_0402_2.2k_+/-5%_50V_0.063W_M_+/-200ppm; MPN Status: ACTIVE; MSL: N/A; MTBF: N/A; MTBF Standard: N/A; Manufacturer: MANUFACTURER SELECTION; Max Oper Temp: +155DEGC; Max TC: +200PPM/DEGC; Max Tol: +5%; Min Oper Temp: -55DEGC; Min TC: -200PPM/DEGC; Min Tol: -5%; Mounting Type: SMD; NOTE Status: PREFERRED; Old Footprint: RESC1005X40N; PCB Package: 0402; Packing Size: 10000; Packing Type: TAPE_&_REEL; Part Number: 01-22350; Part Type: RESISTOR\0402\STANDARD; Resistor Type: THICK FILM; Revision: R000; RoHS Status: ROHS_COMPLIANT; Rtd Current: N/A; Rtd Power: 0.063W; Rtd Voltage: 50V; Vendor: MANUFACTURER SELECTION; Vendor Part Number: RESISTOR_0402_2.2k_+/-5%_50V_0.063W_M_+/-200ppm; Vendor Part Status: ACTIVE; WEIGHT: N/A
R14 = RESISTOR: RESISTOR, THICK FILM, 220, -5%/+5%, 0.063W, 50V, -55DEGC/+155DEGC, 0402, SMD; AutoDoc File: https://notefied-dynamic-precision.com/DB/Apps/Desktop/Item/Object.aspx?id=113319; BU Name: TEXAS INSTRUMENTS NORWAY; Budget Currency: USD; Budget Price: 0.00244; Country of Origin: MISSING INFO; Datasheet URL 1: N/A; Datasheet URL 2: N/A; Definied Quality: INDUSTRIAL; Esd Level: N/A; Last Time Buy: N/A; Lead Time: N/A; LifeCycle Status: ACTIVE; MPN: RESISTOR_0402_220_+/-5%_50V_0.063W_M_+/-200ppm; MPN Status: ACTIVE; MSL: N/A; MTBF: N/A; MTBF Standard: N/A; Manufacturer: MANUFACTURER SELECTION; Max Oper Temp: +155DEGC; Max TC: +200PPM/DEGC; Max Tol: +5%; Min Oper Temp: -55DEGC; Min TC: -200PPM/DEGC; Min Tol: -5%; Mounting Type: SMD; NOTE Status: PREFERRED; Old Footprint: RESC1005X40N; PCB Package: 0402; Packing Size: 10000; Packing Type: TAPE_&_REEL; Part Number: 01-22346; Part Type: RESISTOR\0402\STANDARD; Resistor Type: THICK FILM; Revision: R000; RoHS Status: ROHS_COMPLIANT; Rtd Current: N/A; Rtd Power: 0.063W; Rtd Voltage: 50V; Vendor: MANUFACTURER SELECTION; Vendor Part Number: RESISTOR_0402_220_+/-5%_50V_0.063W_M_+/-200ppm; Vendor Part Status: ACTIVE; WEIGHT: N/A
R15 = RESISTOR: RESISTOR, THICK FILM, 180, -5%/+5%, 0.063W, 50V, -55DEGC/+155DEGC, 0402, SMD; AutoDoc File: https://notefied-dynamic-precision.com/DB/Apps/Desktop/Item/Object.aspx?id=113318; BU Name: TEXAS INSTRUMENTS NORWAY; Budget Currency: USD; Budget Price: 0.00244; Country of Origin: MISSING INFO; Datasheet URL 1: N/A; Datasheet URL 2: N/A; Definied Quality: INDUSTRIAL; Esd Level: N/A; Last Time Buy: N/A; Lead Time: N/A; LifeCycle Status: ACTIVE; MPN: RESISTOR_0402_180_+/-5%_50V_0.063W_M_+/-200ppm; MPN Status: ACTIVE; MSL: N/A; MTBF: N/A; MTBF Standard: N/A; Manufacturer: MANUFACTURER SELECTION; Max Oper Temp: +155DEGC; Max TC: +200PPM/DEGC; Max Tol: +5%; Min Oper Temp: -55DEGC; Min TC: -200PPM/DEGC; Min Tol: -5%; Mounting Type: SMD; NOTE Status: PREFERRED; Old Footprint: RESC1005X40N; PCB Package: 0402; Packing Size: 10000; Packing Type: TAPE_&_REEL; Part Number: 01-22345; Part Type: RESISTOR\0402\STANDARD; Resistor Type: THICK FILM; Revision: R000; RoHS Status: ROHS_COMPLIANT; Rtd Current: N/A; Rtd Power: 0.063W; Rtd Voltage: 50V; Vendor: MANUFACTURER SELECTION; Vendor Part Number: RESISTOR_0402_180_+/-5%_50V_0.063W_M_+/-200ppm; Vendor Part Status: ACTIVE; WEIGHT: N/A
R46-R49 R51 = RESISTOR: RESISTOR, DO NOT MOUNT, 0603, SMD; ALT_SYMBOLS: RESC1608X55L,RESC1608X55M; AutoDoc File: http://notefied-dynamic-precision.com/DB/Apps/Desktop/Item/Object.aspx?id=48377; Budget Currency: N/A; Budget Price: N/A; Datasheet URL 1: N/A; Datasheet URL 2: N/A; Esd Level: N/A; FPLIST: RESC1608X55N,RESC1608X55L,RESC1608X55M; Last Time Buy: N/A; Lead Time: N/A; LifeCycle Status: ACTIVE; MPN Status: ACTIVE; MSL: N/A; MTBF: N/A; MTBF Standard: N/A; Manufacturer: DO NOT MOUNT; Max Oper Temp: N/A; Max TC: N/A; Max Tol: N/A; Min Oper Temp: N/A; Min TC: N/A; Min Tol: N/A; Mounting Type: SMD; NOTE Status: PREFERRED; Old Footprint: RESC1608X55N,0603; PCB Package: 0603; Packing Size: N/A; Part Number: 01-02493; Part Type: RESISTOR\0603\STANDARD; Resistor Type: N/A; Revision: R001; RoHS Status: MISSING_INFO; Rtd Current: N/A; Rtd Power: N/A; Rtd Voltage: N/A; WEIGHT: N/A
R52 = RESISTOR: RESISTOR, THICK FILM, 0, 0.1W, 75V, -55DEGC/+155DEGC, 0603, SMD; ALT_SYMBOLS: RESC1608X55L,RESC1608X55M; AutoDoc File: http://notefied-dynamic-precision.com/DB/Apps/Desktop/Item/Object.aspx?id=75812; Budget Currency: USD; Budget Price: 0.00262; Datasheet URL 1: N/A; Datasheet URL 2: N/A; Definied Quality: INDUSTRIAL; Esd Level: N/A; FPLIST: RESC1608X55N,RESC1608X55L,RESC1608X55M; Last Time Buy: N/A; Lead Time: N/A; LifeCycle Status: ACTIVE; MPN: RESISTOR_0603_0_+/-5%_75V_0.1W_M_+/-200ppm; MPN Status: ACTIVE; MSL: N/A; MTBF: N/A; MTBF Standard: N/A; Manufacturer: MANUFACTURER SELECTION; Max Oper Temp: +155DEGC; Max TC: +200PPM/DEGC; Max Tol: N/A; Min Oper Temp: -55DEGC; Min TC: -200PPM/DEGC; Min Tol: N/A; Mounting Type: SMD; NOTE Status: PREFERRED; PCB Package: 0603; Packing Size: 5000; Packing Type: TAPE_&_REEL; Part Number: 01-11757; Part Type: RESISTOR\0603\JUMPER; Resistor Type: THICK FILM; Revision: R000; RoHS Status: ROHS_COMPLIANT; Rtd Current: N/A; Rtd Power: 0.1W; Rtd Voltage: 75V; WEIGHT: 0.002g
R55 R56 = RESISTOR: RESISTOR, THICK FILM, 100, -5%/+5%, 0.063W, 50V, -55DEGC/+155DEGC, 0402, SMD; AutoDoc File: https://notefied-dynamic-precision.com/DB/Apps/Desktop/Item/Object.aspx?id=113316; BU Name: TEXAS INSTRUMENTS NORWAY; Budget Currency: USD; Budget Price: 0.00244; Country of Origin: MISSING INFO; Datasheet URL 1: N/A; Datasheet URL 2: N/A; Definied Quality: INDUSTRIAL; Esd Level: N/A; Last Time Buy: N/A; Lead Time: N/A; LifeCycle Status: ACTIVE; MPN: RESISTOR_0402_100_+/-5%_50V_0.063W_M_+/-200ppm; MPN Status: ACTIVE; MSL: N/A; MTBF: N/A; MTBF Standard: N/A; Manufacturer: MANUFACTURER SELECTION; Max Oper Temp: +155DEGC; Max TC: +200PPM/DEGC; Max Tol: +5%; Min Oper Temp: -55DEGC; Min TC: -200PPM/DEGC; Min Tol: -5%; Mounting Type: SMD; NOTE Status: PREFERRED; Old Footprint: RESC1005X40N; PCB Package: 0402; Packing Size: 10000; Packing Type: TAPE_&_REEL; Part Number: 01-22343; Part Type: RESISTOR\0402\STANDARD; Resistor Type: THICK FILM; Revision: R000; RoHS Status: ROHS_COMPLIANT; Rtd Current: N/A; Rtd Power: 0.063W; Rtd Voltage: 50V; Vendor: MANUFACTURER SELECTION; Vendor Part Number: RESISTOR_0402_100_+/-5%_50V_0.063W_M_+/-200ppm; Vendor Part Status: ACTIVE; WEIGHT: N/A
R59 R60 = RESISTOR: RESISTOR, DO NOT MOUNT, 0402, SMD; AutoDoc File: https://notefied-dynamic-precision.com/DB/Apps/Desktop/Item/Object.aspx?id=113312; BU Name: TEXAS INSTRUMENTS NORWAY; Budget Currency: N/A; Budget Price: N/A; Country of Origin: MISSING INFO; Datasheet URL 1: N/A; Datasheet URL 2: N/A; Esd Level: N/A; Last Time Buy: N/A; Lead Time: N/A; LifeCycle Status: ACTIVE; MPN Status: ACTIVE; MSL: N/A; MTBF: N/A; MTBF Standard: N/A; Manufacturer: DO NOT MOUNT; Max Oper Temp: N/A; Max TC: N/A; Max Tol: N/A; Min Oper Temp: N/A; Min TC: N/A; Min Tol: N/A; Mounting Type: SMD; NOTE Status: PREFERRED; Old Footprint: RESC1005X40N,0402; PCB Package: 0402; Packing Size: N/A; Part Number: 01-22339; Part Type: RESISTOR\0402\STANDARD; Resistance: N/A; Resistor Type: THICK FILM; Revision: R000; RoHS Status: MISSING_INFO; Rtd Current: N/A; Rtd Power: N/A; Rtd Voltage: N/A; Vendor: DO NOT MOUNT; Vendor Part Status: ACTIVE; WEIGHT: N/A
SW1 SW2 = SWITCH_TACT_V2: SWITCH, TACT, 0.05A@250VAC, 0.05A@12VDC, 0.05A, 250V, SMD; ALT_SYMBOLS: SW_1188E1K2V_A2L,SW_1188E1K2V_A2M; AutoDoc File: http://notefied-dynamic-precision.com/DB/Apps/Desktop/Item/Object.aspx?id=104642; Datasheet URL 1: N/A; Datasheet URL 2: http://www.dip.com.tw/en/en-product-information/en-switch004; FPLIST: SW_1188E1K2V_A2N,SW_1188E1K2V_A2L,SW_1188E1K2V_A2M; MPN: 1188E-1K2-V-TR; MPN Status: ACTIVE; Manufacturer: DIPTRONICS; Max Oper Temp: +70DEGC; Min Oper Temp: -25DEGC; Mounting Type: SMD; NOTE Status: PREFERRED; Packing Size: 1500; Packing Type: TAPE_&_REEL; Part Number: 08-00293; Part Type: SWITCH\TACT; Revision: R001; RoHS Status: ROHS_COMPLIANT; Rtd Current: 0.05A; Rtd Voltage: 12V
U4 = IC_FLASH_MX25R8035F_USON8: IC, MEMORY, FLASH, SERIAL, 8Mbit, 1.65V TO 3.6V, USON8, SMD; ALT_SYMBOLS: SON50P300X200X60-9B2L,SON50P300X200X60-9B2M; AutoDoc File: http://notefied-dynamic-precision.com/DB/Apps/Desktop/Item/Object.aspx?id=104624; Datasheet URL 1: N/A; Datasheet URL 2: http://www.macronix.com/Lists/DataSheet/Attachments/2570/MX25R8035F,%20Wide%20Range,%208Mb,%20v0.04.pdf; FPLIST: SON50P300X200X60-9B2N,SON50P300X200X60-9B2L,SON50P300X200X60-9B2M; MPN Status: ACTIVE; Manufacturer: MACRONIX; Max Oper Temp: +85DEGC; Min Oper Temp: -40DEGC; Mounting Type: SMD; NOTE Status: PREFERRED; Old Footprint: SON50P300X200X60-9B2N; PCB Package: USON8; Part Number: 18-31726; Part Type: IC\MEMORY\FLASH\OTHER; Revision: R001; RoHS Status: ROHS_COMPLIANT; Rtd Voltage: 1.65V TO 3.6V

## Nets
+5V: J1.2 P2.1 ; also on sheet 2
GND: A1.2(GND) A1.3(GND) C3.2 C4.2 C5.2 C6.2 C7.2 C8.2 C9.2 C12.2 C13.1 C15.2 C16.2 C17.2 C18.2 C19.2 C20.2 C21.1 C30.2 C31.2 CR1.1(C) CR2.1(C) J1.4 J2.2 P1.2 P1.3 P2.2 P2.3 P11.2 P11.M1 P11.M2 SW1.1 SW1.2 SW1.3 SW2.1 SW2.2 SW2.4 U1.49(VSS) U4.4(GND) U4.9(EGP) Y2.2 Y2.4 ; also on sheet 1 2 3
VDDR: C8.1 C9.1 C16.1 L1.2 U1.45(VDDR) U1.48(VDDR)
VDDS: C3.1 C4.1 C5.1 C6.1 C7.1 FL1.1 R1.2 U1.13(VDDS2) U1.22(VDDS3) U1.34(VDDS_DCDC) U1.44(VDDS)
BP_RESET: J2.11 R52.2
CC2650_RESET: C20.1 R1.1 R51.2 R52.1 U1.35(RESET_N) ; also on sheet 2
CC2650_RXD: J1.7 U1.7(DIO_2) ; also on sheet 2
CC2650_SWO: J2.9 U1.28(DIO_18) ; also on sheet 2
CC2650_TCK: R47.2 U1.25(JTAG_TCKC) ; also on sheet 2
CC2650_TMS: R46.2 U1.24(JTAG_TMSC) ; also on sheet 2
CC2650_TXD: J1.5 U1.8(DIO_3) ; also on sheet 2
CC2650_VDD: C30.1 FL1.2 J1.1 P1.1 R2.2 R3.2 R11.2 R59.2 R60.2 U4.8(VCC) ; also on sheet 2
DCDC_SW: L1.1 U1.33(DCDC_SW)
DIO0: J1.18 U1.5(DIO_0)
DIO1: J1.20 U1.6(DIO_1)
DIO4_SCL: J1.17 R2.1 U1.9(DIO_4)
DIO5_SDA: J1.19 R3.1 U1.10(DIO_5)
DIO6_RLED: J2.3 P6.2 U1.11(DIO_6)
DIO7_GLED: J2.1 P6.4 U1.12(DIO_7)
DIO8_MISO: J2.14 U1.14(DIO_8) U4.2(SO/SIO1)
DIO9_MOSI: J2.12 U1.15(DIO_9) U4.5(SI/SIO0)
DIO10_SCLK: J1.13 U1.16(DIO_10) U4.6(SCLK)
DIO11_CS: J2.6 U1.17(DIO_11)
DIO12: J2.4 U1.18(DIO_12)
DIO13_BTN1: J2.16 R56.2 U1.19(DIO_13)
DIO14_BTN2: J2.18 R55.2 U1.20(DIO_14)
DIO15: J2.20 U1.21(DIO_15)
DIO16_TDO: R48.2 U1.26(DIO_16) ; also on sheet 2
DIO17_TDI: R49.2 U1.27(DIO_17) ; also on sheet 2
DIO19_CTS: J2.7 U1.29(DIO_19)
DIO20_Flash_CS: J2.5 R11.1 U1.30(DIO_20) U4.1(nCS)
DIO21: J1.15 U1.31(DIO_21)
DIO22: J1.9 U1.32(DIO_22)
DIO23_Analog: J1.3 U1.36(DIO_23)
DIO24_Analog: J1.11 U1.37(DIO_24)
DIO25_Analog: J1.6 U1.38(DIO_25)
DIO26_Analog: J1.8 U1.39(DIO_26)
DIO27_Analog: J1.10 U1.40(DIO_27)
DIO28_Analog: J1.12 U1.41(DIO_28)
DIO29_Analog: J1.14 U1.42(DIO_29)
DIO30_Analog: J1.16 U1.43(DIO_30)
LP_RESET: J2.10 R51.1
N1013277: U1.46(X24M_N) Y2.3
N1013851: C21.2 L21.1 U1.2(RF_N)
N1013859: C11.1 L11.1 U1.1(RF_P)
N1013883: C31.1 L11.2
N1013899: C11.2 C12.1 L12.1 L21.2
N1013927: C13.2 L12.2 L13.1
N1013977: A1.1(FEED) C15.1 C51.2
N1014081: C19.1 U1.23(DCOUPL)
N1014101: C17.1 U1.3(X32K_Q1) Y1.1
N1014113: C18.1 U1.4(X32K_Q2) Y1.2
N1014125: C24.1 C51.1 C58.2
N1014335: C24.2 L13.2
N1018937: U1.47(X24M_P) Y2.1
N1105722: CR1.2(A) R15.1
N1105771: CR2.2(A) R14.1
N1105824: P6.1 R14.2
N1106228: P6.3 R15.2
N1176544: J2.13 R46.1
N1176548: J2.15 R47.1
N1176568: J2.17 R48.1
N1177007: J2.19 R49.1
N1288065: R55.1 SW2.3
N1288098: R56.1 SW1.4
N1409884: R59.1 U4.3(nWP/SIO2)
N1409917: R60.1 U4.7(nRST/SIO3)
N1429173: C58.1 P11.1

Not connected (* = marked no-connect by the designer): J2 8

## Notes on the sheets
sheet 4
- BoosterPack Headers and Peripherals
- 1
- 21
- 40
- 20
- 2
- 22
- 39
- 19
- 5V and 3V header
- 3
- 23
- 38
- 18
- 4
- 24
- 37
- 17
- 5
- 6
- 25
- 26
- 35
- 36
- 15
- 16
- 7
- 27
- 34
- 14
- 8
- 28
- 33
- 13
- 9
- 29
- 32
- 12
- 10
- 30
- 31
- 11
- Jumpers to be mounted on P6
- CC2650 IO block
- External flash
sheet 5
- CC2650 RF
- VDDS Decoupling Capacitors
- VDDR Decoupling Capacitors
- Pin 13
- Pin 22
- Pin 44
- Pin 34
- Pin 45
- Pin 48
- Place L1 and
  C8 close to pin 33
- C51 and C15 for
  antenna matching
- CC2650 IO block
  placed on page 2.
